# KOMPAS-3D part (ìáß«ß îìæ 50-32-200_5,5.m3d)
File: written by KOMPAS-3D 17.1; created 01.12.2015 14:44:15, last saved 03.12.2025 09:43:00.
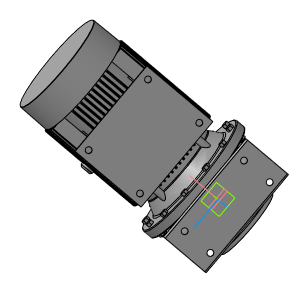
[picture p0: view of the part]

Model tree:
1. Операция без истории:3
